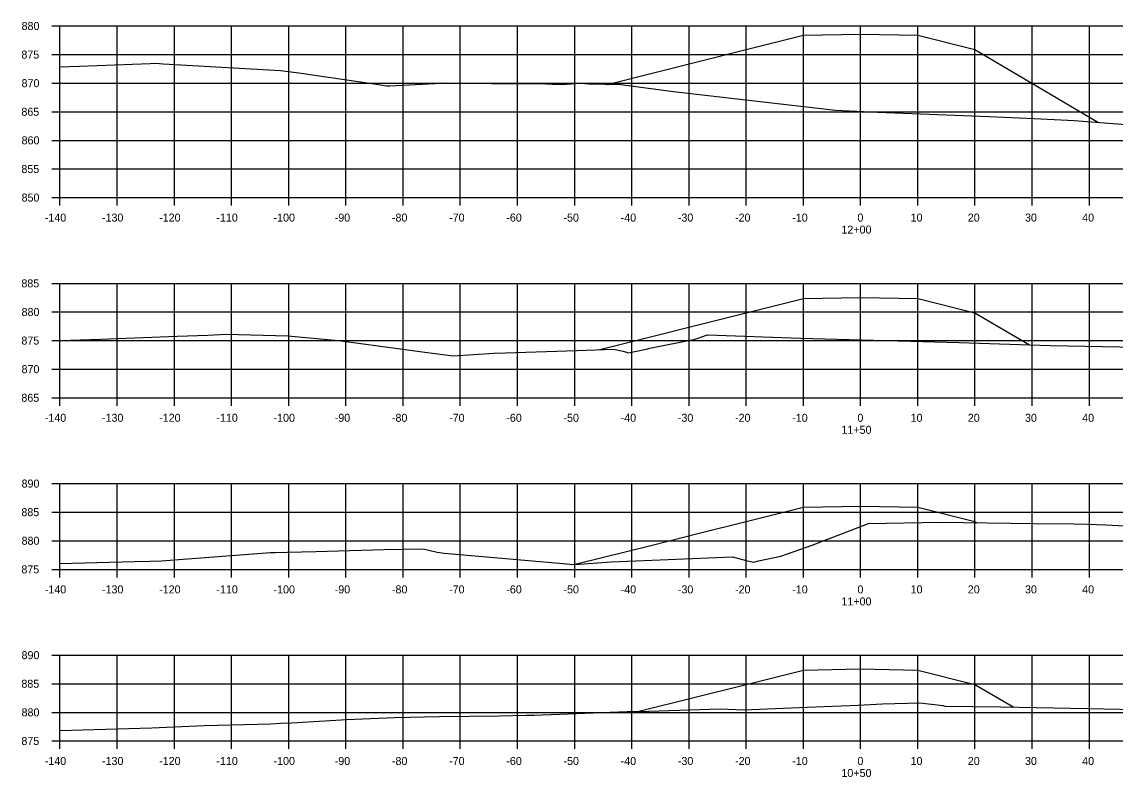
# Model space of a CAD drawing. Extents: x 1098669 to 1198896, y 698679 to 704410.
# Drawn here: x 1110634.5 to 1110825.7, y 701652.8 to 701784.8 of the extents above; entities that cross this region are included whole.
import ezdxf

# ---------------------------------------------------------------- set-up
doc = ezdxf.new("R2010")
doc.units = 0
for name, color, linetype in [('Proposed Surface', 7, 'Continuous'), ('R_Axis', 7, 'Continuous'), ('R_Axis Annot', 7, 'Continuous'), ('R_Fin Surface', 7, 'Continuous'), ('R_Grid', 7, 'Continuous')]:
    doc.layers.add(name, color=color, linetype=linetype)

msp = doc.modelspace()

# ---------------------------------------------------------------- linework, layer by layer
at = {"layer": 'Proposed Surface'}
for points in [[(1110641.16, 701777.01), (1110644.58, 701777.09), (1110656.9, 701777.56), (1110657.91, 701777.6), (1110659.22, 701777.52), (1110679.74, 701776.34), (1110682.93, 701775.94), (1110696.1, 701774), (1110697.88, 701773.74), (1110698.32, 701773.67), (1110698.85, 701773.69), (1110708.98, 701774.17), (1110716.6, 701774.06), (1110725.18, 701774.08), (1110727.28, 701773.95), (1110728.95, 701773.9), (1110731.29, 701774.08), (1110732.23, 701774.11), (1110733.55, 701774), (1110739.23, 701773.87), (1110748.41, 701772.69), (1110776.76, 701769.4), (1110784.13, 701769.05), (1110803.65, 701768.28), (1110811.52, 701767.97), (1110818.51, 701767.61), (1110851.8, 701765.03)], [(1110641.16, 701729.16), (1110648.32, 701729.35), (1110661.64, 701729.88), (1110666.99, 701730.08), (1110670.21, 701730.23), (1110681.02, 701729.94), (1110689.84, 701729.12), (1110690.3, 701729.08), (1110704.09, 701727.22), (1110709.94, 701726.49), (1110717.04, 701726.9), (1110719.06, 701727.01), (1110731.6, 701727.38), (1110737.93, 701727.61), (1110739.61, 701727.29), (1110740.56, 701726.98), (1110743.66, 701727.64), (1110744.3, 701727.81), (1110752.22, 701729.36), (1110754.4, 701730.11), (1110770.67, 701729.54), (1110798.38, 701728.78), (1110814.33, 701728.24), (1110832.59, 701727.9)], [(1110641.16, 701690.17), (1110654.19, 701690.48), (1110656.9, 701690.54), (1110658.9, 701690.6), (1110677.95, 701692.06), (1110678.78, 701692.1), (1110680.9, 701692.14), (1110685.87, 701692.23), (1110687.9, 701692.3), (1110697.84, 701692.62), (1110704.66, 701692.73), (1110707.09, 701692.12), (1110708.34, 701691.96), (1110729.12, 701690.14), (1110730.31, 701690.05), (1110731.16, 701689.99), (1110732, 701690.04), (1110737.55, 701690.43), (1110741.86, 701690.64), (1110747.52, 701690.87), (1110758.76, 701691.33), (1110761.17, 701690.68), (1110762.41, 701690.36), (1110763.31, 701690.61), (1110767.22, 701691.42), (1110772.71, 701693.36), (1110782.52, 701697.12), (1110795.05, 701697.39), (1110811.45, 701697.14), (1110818.44, 701697.08), (1110820.76, 701697.05), (1110824.05, 701696.94), (1110838.5, 701696.15)], [(1110641.16, 701660.94), (1110657.21, 701661.41), (1110666.36, 701661.86), (1110678, 701662.15), (1110679.72, 701662.25), (1110681.63, 701662.3), (1110691.34, 701662.88), (1110699.68, 701663.22), (1110707.55, 701663.38), (1110717.97, 701663.55), (1110722.68, 701663.63), (1110724.08, 701663.65), (1110740.32, 701664.3), (1110744.13, 701664.35), (1110756.61, 701664.73), (1110760.67, 701664.55), (1110771.81, 701665.05), (1110780.71, 701665.38), (1110785, 701665.62), (1110791.53, 701665.78), (1110795.05, 701665.38), (1110795.41, 701665.34), (1110795.55, 701665.32), (1110795.93, 701665.24), (1110805.6, 701665.08), (1110811.86, 701664.96), (1110820.88, 701664.81), (1110832.15, 701664.6)]]:
    msp.add_lwpolyline(points, dxfattribs=at)
at = {"layer": 'R_Axis'}
for p, q in [((1110639.76, 701784.13), (1110641.16, 701784.13)), ((1110641.16, 701754.13), (1110641.16, 701784.13)), ((1110639.76, 701779.13), (1110641.16, 701779.13)), ((1110639.76, 701774.13), (1110641.16, 701774.13)), ((1110639.76, 701769.13), (1110641.16, 701769.13)), ((1110639.76, 701764.13), (1110641.16, 701764.13)), ((1110639.76, 701759.13), (1110641.16, 701759.13)), ((1110639.76, 701754.13), (1110641.16, 701754.13)), ((1110641.16, 701754.13), (1110921.16, 701754.13)), ((1110641.16, 701752.73), (1110641.16, 701754.13)), ((1110651.16, 701752.73), (1110651.16, 701754.13)), ((1110661.16, 701752.73), (1110661.16, 701754.13)), ((1110671.16, 701752.73), (1110671.16, 701754.13)), ((1110681.16, 701752.73), (1110681.16, 701754.13)), ((1110691.16, 701752.73), (1110691.16, 701754.13)), ((1110701.16, 701752.73), (1110701.16, 701754.13)), ((1110711.16, 701752.73), (1110711.16, 701754.13)), ((1110721.16, 701752.73), (1110721.16, 701754.13)), ((1110731.16, 701752.73), (1110731.16, 701754.13)), ((1110741.16, 701752.73), (1110741.16, 701754.13)), ((1110751.16, 701752.73), (1110751.16, 701754.13)), ((1110761.16, 701752.73), (1110761.16, 701754.13)), ((1110771.16, 701752.73), (1110771.16, 701754.13)), ((1110781.16, 701752.73), (1110781.16, 701754.13)), ((1110791.16, 701752.73), (1110791.16, 701754.13)), ((1110801.16, 701752.73), (1110801.16, 701754.13)), ((1110811.16, 701752.73), (1110811.16, 701754.13)), ((1110821.16, 701752.73), (1110821.16, 701754.13)), ((1110639.76, 701739.13), (1110641.16, 701739.13)), ((1110641.16, 701719.13), (1110641.16, 701739.13)), ((1110639.76, 701734.13), (1110641.16, 701734.13)), ((1110639.76, 701729.13), (1110641.16, 701729.13)), ((1110639.76, 701724.13), (1110641.16, 701724.13)), ((1110639.76, 701719.13), (1110641.16, 701719.13)), ((1110641.16, 701719.13), (1110921.16, 701719.13)), ((1110641.16, 701717.73), (1110641.16, 701719.13)), ((1110651.16, 701717.73), (1110651.16, 701719.13)), ((1110661.16, 701717.73), (1110661.16, 701719.13)), ((1110671.16, 701717.73), (1110671.16, 701719.13)), ((1110681.16, 701717.73), (1110681.16, 701719.13)), ((1110691.16, 701717.73), (1110691.16, 701719.13)), ((1110701.16, 701717.73), (1110701.16, 701719.13)), ((1110711.16, 701717.73), (1110711.16, 701719.13)), ((1110721.16, 701717.73), (1110721.16, 701719.13)), ((1110731.16, 701717.73), (1110731.16, 701719.13)), ((1110741.16, 701717.73), (1110741.16, 701719.13)), ((1110751.16, 701717.73), (1110751.16, 701719.13)), ((1110761.16, 701717.73), (1110761.16, 701719.13)), ((1110771.16, 701717.73), (1110771.16, 701719.13)), ((1110781.16, 701717.73), (1110781.16, 701719.13)), ((1110791.16, 701717.73), (1110791.16, 701719.13)), ((1110801.16, 701717.73), (1110801.16, 701719.13)), ((1110811.16, 701717.73), (1110811.16, 701719.13)), ((1110821.16, 701717.73), (1110821.16, 701719.13)), ((1110639.76, 701704.13), (1110641.16, 701704.13)), ((1110641.16, 701689.13), (1110641.16, 701704.13)), ((1110639.76, 701699.13), (1110641.16, 701699.13)), ((1110639.76, 701694.13), (1110641.16, 701694.13)), ((1110639.76, 701689.13), (1110641.16, 701689.13)), ((1110641.16, 701689.13), (1110921.16, 701689.13)), ((1110641.16, 701687.73), (1110641.16, 701689.13)), ((1110651.16, 701687.73), (1110651.16, 701689.13)), ((1110661.16, 701687.73), (1110661.16, 701689.13)), ((1110671.16, 701687.73), (1110671.16, 701689.13)), ((1110681.16, 701687.73), (1110681.16, 701689.13)), ((1110691.16, 701687.73), (1110691.16, 701689.13)), ((1110701.16, 701687.73), (1110701.16, 701689.13)), ((1110711.16, 701687.73), (1110711.16, 701689.13)), ((1110721.16, 701687.73), (1110721.16, 701689.13)), ((1110731.16, 701687.73), (1110731.16, 701689.13)), ((1110741.16, 701687.73), (1110741.16, 701689.13)), ((1110751.16, 701687.73), (1110751.16, 701689.13)), ((1110761.16, 701687.73), (1110761.16, 701689.13)), ((1110771.16, 701687.73), (1110771.16, 701689.13)), ((1110781.16, 701687.73), (1110781.16, 701689.13)), ((1110791.16, 701687.73), (1110791.16, 701689.13)), ((1110801.16, 701687.73), (1110801.16, 701689.13)), ((1110811.16, 701687.73), (1110811.16, 701689.13)), ((1110821.16, 701687.73), (1110821.16, 701689.13)), ((1110639.76, 701674.13), (1110641.16, 701674.13)), ((1110641.16, 701659.13), (1110641.16, 701674.13)), ((1110639.76, 701669.13), (1110641.16, 701669.13)), ((1110639.76, 701664.13), (1110641.16, 701664.13)), ((1110639.76, 701659.13), (1110641.16, 701659.13)), ((1110641.16, 701659.13), (1110921.16, 701659.13)), ((1110641.16, 701657.73), (1110641.16, 701659.13)), ((1110651.16, 701657.73), (1110651.16, 701659.13)), ((1110661.16, 701657.73), (1110661.16, 701659.13)), ((1110671.16, 701657.73), (1110671.16, 701659.13)), ((1110681.16, 701657.73), (1110681.16, 701659.13)), ((1110691.16, 701657.73), (1110691.16, 701659.13)), ((1110701.16, 701657.73), (1110701.16, 701659.13)), ((1110711.16, 701657.73), (1110711.16, 701659.13)), ((1110721.16, 701657.73), (1110721.16, 701659.13)), ((1110731.16, 701657.73), (1110731.16, 701659.13)), ((1110741.16, 701657.73), (1110741.16, 701659.13)), ((1110751.16, 701657.73), (1110751.16, 701659.13)), ((1110761.16, 701657.73), (1110761.16, 701659.13)), ((1110771.16, 701657.73), (1110771.16, 701659.13)), ((1110781.16, 701657.73), (1110781.16, 701659.13)), ((1110791.16, 701657.73), (1110791.16, 701659.13)), ((1110801.16, 701657.73), (1110801.16, 701659.13)), ((1110811.16, 701657.73), (1110811.16, 701659.13)), ((1110821.16, 701657.73), (1110821.16, 701659.13))]:
    msp.add_line(p, q, dxfattribs=at)
at = {"layer": 'R_Fin Surface'}
for points in [[(1110736.84, 701773.92), (1110761.16, 701780), (1110771.16, 701782.5), (1110781.16, 701782.7), (1110791.16, 701782.5), (1110801.16, 701780), (1110808.55, 701775.64), (1110822.74, 701767.28)], [(1110735.31, 701727.51), (1110761.16, 701733.98), (1110771.16, 701736.48), (1110781.16, 701736.68), (1110791.16, 701736.48), (1110801.16, 701733.98), (1110810.68, 701728.36)], [(1110731.16, 701689.99), (1110731.38, 701690.05), (1110731.5, 701690.08), (1110744.68, 701693.38), (1110752.9, 701695.43), (1110761.16, 701697.49), (1110771.16, 701699.99), (1110781.16, 701700.19), (1110791.16, 701699.99), (1110801.16, 701697.49), (1110801.5, 701697.29)], [(1110742.35, 701664.33), (1110761.16, 701669.03), (1110771.16, 701671.53), (1110781.16, 701671.73), (1110791.16, 701671.53), (1110801.16, 701669.03), (1110807.93, 701665.04)]]:
    msp.add_lwpolyline(points, dxfattribs=at)
at = {"layer": 'R_Grid'}
for p, q in [((1110641.16, 701784.13), (1110921.16, 701784.13)), ((1110641.16, 701754.13), (1110641.16, 701784.13)), ((1110651.16, 701754.13), (1110651.16, 701784.13)), ((1110661.16, 701754.13), (1110661.16, 701784.13)), ((1110671.16, 701754.13), (1110671.16, 701784.13)), ((1110681.16, 701754.13), (1110681.16, 701784.13)), ((1110691.16, 701754.13), (1110691.16, 701784.13)), ((1110701.16, 701754.13), (1110701.16, 701784.13)), ((1110711.16, 701754.13), (1110711.16, 701784.13)), ((1110721.16, 701754.13), (1110721.16, 701784.13)), ((1110731.16, 701754.13), (1110731.16, 701784.13)), ((1110741.16, 701754.13), (1110741.16, 701784.13)), ((1110751.16, 701754.13), (1110751.16, 701784.13)), ((1110761.16, 701754.13), (1110761.16, 701784.13)), ((1110771.16, 701754.13), (1110771.16, 701784.13)), ((1110781.16, 701754.13), (1110781.16, 701784.13)), ((1110791.16, 701754.13), (1110791.16, 701784.13)), ((1110801.16, 701754.13), (1110801.16, 701784.13)), ((1110811.16, 701754.13), (1110811.16, 701784.13)), ((1110821.16, 701754.13), (1110821.16, 701784.13)), ((1110641.16, 701779.13), (1110921.16, 701779.13)), ((1110641.16, 701774.13), (1110921.16, 701774.13)), ((1110641.16, 701769.13), (1110921.16, 701769.13)), ((1110641.16, 701764.13), (1110921.16, 701764.13)), ((1110641.16, 701759.13), (1110921.16, 701759.13)), ((1110641.16, 701754.13), (1110921.16, 701754.13)), ((1110641.16, 701739.13), (1110921.16, 701739.13)), ((1110641.16, 701719.13), (1110641.16, 701739.13)), ((1110651.16, 701719.13), (1110651.16, 701739.13)), ((1110661.16, 701719.13), (1110661.16, 701739.13)), ((1110671.16, 701719.13), (1110671.16, 701739.13)), ((1110681.16, 701719.13), (1110681.16, 701739.13)), ((1110691.16, 701719.13), (1110691.16, 701739.13)), ((1110701.16, 701719.13), (1110701.16, 701739.13)), ((1110711.16, 701719.13), (1110711.16, 701739.13)), ((1110721.16, 701719.13), (1110721.16, 701739.13)), ((1110731.16, 701719.13), (1110731.16, 701739.13)), ((1110741.16, 701719.13), (1110741.16, 701739.13)), ((1110751.16, 701719.13), (1110751.16, 701739.13)), ((1110761.16, 701719.13), (1110761.16, 701739.13)), ((1110771.16, 701719.13), (1110771.16, 701739.13)), ((1110781.16, 701719.13), (1110781.16, 701739.13)), ((1110791.16, 701719.13), (1110791.16, 701739.13)), ((1110801.16, 701719.13), (1110801.16, 701739.13)), ((1110811.16, 701719.13), (1110811.16, 701739.13)), ((1110821.16, 701719.13), (1110821.16, 701739.13)), ((1110641.16, 701734.13), (1110921.16, 701734.13)), ((1110641.16, 701729.13), (1110921.16, 701729.13)), ((1110641.16, 701724.13), (1110921.16, 701724.13)), ((1110641.16, 701719.13), (1110921.16, 701719.13)), ((1110641.16, 701704.13), (1110921.16, 701704.13)), ((1110641.16, 701689.13), (1110641.16, 701704.13)), ((1110651.16, 701689.13), (1110651.16, 701704.13)), ((1110661.16, 701689.13), (1110661.16, 701704.13)), ((1110671.16, 701689.13), (1110671.16, 701704.13)), ((1110681.16, 701689.13), (1110681.16, 701704.13)), ((1110691.16, 701689.13), (1110691.16, 701704.13)), ((1110701.16, 701689.13), (1110701.16, 701704.13)), ((1110711.16, 701689.13), (1110711.16, 701704.13)), ((1110721.16, 701689.13), (1110721.16, 701704.13)), ((1110731.16, 701689.13), (1110731.16, 701704.13)), ((1110741.16, 701689.13), (1110741.16, 701704.13)), ((1110751.16, 701689.13), (1110751.16, 701704.13)), ((1110761.16, 701689.13), (1110761.16, 701704.13)), ((1110771.16, 701689.13), (1110771.16, 701704.13)), ((1110781.16, 701689.13), (1110781.16, 701704.13)), ((1110791.16, 701689.13), (1110791.16, 701704.13)), ((1110801.16, 701689.13), (1110801.16, 701704.13)), ((1110811.16, 701689.13), (1110811.16, 701704.13)), ((1110821.16, 701689.13), (1110821.16, 701704.13)), ((1110641.16, 701699.13), (1110921.16, 701699.13)), ((1110641.16, 701694.13), (1110921.16, 701694.13)), ((1110641.16, 701689.13), (1110921.16, 701689.13)), ((1110641.16, 701674.13), (1110921.16, 701674.13)), ((1110641.16, 701659.13), (1110641.16, 701674.13)), ((1110651.16, 701659.13), (1110651.16, 701674.13)), ((1110661.16, 701659.13), (1110661.16, 701674.13)), ((1110671.16, 701659.13), (1110671.16, 701674.13)), ((1110681.16, 701659.13), (1110681.16, 701674.13)), ((1110691.16, 701659.13), (1110691.16, 701674.13)), ((1110701.16, 701659.13), (1110701.16, 701674.13)), ((1110711.16, 701659.13), (1110711.16, 701674.13)), ((1110721.16, 701659.13), (1110721.16, 701674.13)), ((1110731.16, 701659.13), (1110731.16, 701674.13)), ((1110741.16, 701659.13), (1110741.16, 701674.13)), ((1110751.16, 701659.13), (1110751.16, 701674.13)), ((1110761.16, 701659.13), (1110761.16, 701674.13)), ((1110771.16, 701659.13), (1110771.16, 701674.13)), ((1110781.16, 701659.13), (1110781.16, 701674.13)), ((1110791.16, 701659.13), (1110791.16, 701674.13)), ((1110801.16, 701659.13), (1110801.16, 701674.13)), ((1110811.16, 701659.13), (1110811.16, 701674.13)), ((1110821.16, 701659.13), (1110821.16, 701674.13)), ((1110641.16, 701669.13), (1110921.16, 701669.13)), ((1110641.16, 701664.13), (1110921.16, 701664.13)), ((1110641.16, 701659.13), (1110921.16, 701659.13))]:
    msp.add_line(p, q, dxfattribs=at)

# ---------------------------------------------------------------- texts
at = {"layer": 'R_Axis Annot'}
for s, p in [('880', (1110634.44, 701783.43)), ('875', (1110634.41, 701778.43)), ('870', (1110634.44, 701773.43)), ('865', (1110634.41, 701768.43)), ('860', (1110634.44, 701763.43)), ('855', (1110634.41, 701758.43)), ('850', (1110634.44, 701753.43)), ('-140', (1110638.5, 701749.93)), ('-130', (1110648.5, 701749.93)), ('-120', (1110658.5, 701749.93)), ('-110', (1110668.5, 701749.93)), ('-100', (1110678.5, 701749.93)), ('-90', (1110689.2, 701749.93)), ('-80', (1110699.2, 701749.93)), ('-70', (1110709.2, 701749.93)), ('-60', (1110719.2, 701749.93)), ('-50', (1110729.2, 701749.93)), ('-40', (1110739.2, 701749.93)), ('-30', (1110749.2, 701749.93)), ('-20', (1110759.2, 701749.93)), ('-10', (1110769.2, 701749.93)), ('0', (1110780.6, 701749.93)), ('10', (1110789.9, 701749.93)), ('20', (1110799.9, 701749.93)), ('30', (1110809.9, 701749.93)), ('40', (1110819.9, 701749.93)), ('12+00', (1110777.8, 701747.83)), ('885', (1110634.41, 701738.43)), ('880', (1110634.44, 701733.43)), ('875', (1110634.41, 701728.43)), ('870', (1110634.44, 701723.43)), ('865', (1110634.41, 701718.43)), ('-140', (1110638.5, 701714.93)), ('-130', (1110648.5, 701714.93)), ('-120', (1110658.5, 701714.93)), ('-110', (1110668.5, 701714.93)), ('-100', (1110678.5, 701714.93)), ('-90', (1110689.2, 701714.93)), ('-80', (1110699.2, 701714.93)), ('-70', (1110709.2, 701714.93)), ('-60', (1110719.2, 701714.93)), ('-50', (1110729.2, 701714.93)), ('-40', (1110739.2, 701714.93)), ('-30', (1110749.2, 701714.93)), ('-20', (1110759.2, 701714.93)), ('-10', (1110769.2, 701714.93)), ('0', (1110780.6, 701714.93)), ('10', (1110789.9, 701714.93)), ('20', (1110799.9, 701714.93)), ('30', (1110809.9, 701714.93)), ('40', (1110819.9, 701714.93)), ('11+50', (1110777.8, 701712.83)), ('890', (1110634.44, 701703.43)), ('885', (1110634.41, 701698.43)), ('880', (1110634.44, 701693.43)), ('875', (1110634.41, 701688.43)), ('-140', (1110638.5, 701684.93)), ('-130', (1110648.5, 701684.93)), ('-120', (1110658.5, 701684.93)), ('-110', (1110668.5, 701684.93)), ('-100', (1110678.5, 701684.93)), ('-90', (1110689.2, 701684.93)), ('-80', (1110699.2, 701684.93)), ('-70', (1110709.2, 701684.93)), ('-60', (1110719.2, 701684.93)), ('-50', (1110729.2, 701684.93)), ('-40', (1110739.2, 701684.93)), ('-30', (1110749.2, 701684.93)), ('-20', (1110759.2, 701684.93)), ('-10', (1110769.2, 701684.93)), ('0', (1110780.6, 701684.93)), ('10', (1110789.9, 701684.93)), ('20', (1110799.9, 701684.93)), ('30', (1110809.9, 701684.93)), ('40', (1110819.9, 701684.93)), ('11+00', (1110777.8, 701682.83)), ('890', (1110634.44, 701673.43)), ('885', (1110634.41, 701668.43)), ('880', (1110634.44, 701663.43)), ('875', (1110634.41, 701658.43)), ('-140', (1110638.5, 701654.93)), ('-130', (1110648.5, 701654.93)), ('-120', (1110658.5, 701654.93)), ('-110', (1110668.5, 701654.93)), ('-100', (1110678.5, 701654.93)), ('-90', (1110689.2, 701654.93)), ('-80', (1110699.2, 701654.93)), ('-70', (1110709.2, 701654.93)), ('-60', (1110719.2, 701654.93)), ('-50', (1110729.2, 701654.93)), ('-40', (1110739.2, 701654.93)), ('-30', (1110749.2, 701654.93)), ('-20', (1110759.2, 701654.93)), ('-10', (1110769.2, 701654.93)), ('0', (1110780.6, 701654.93)), ('10', (1110789.9, 701654.93)), ('20', (1110799.9, 701654.93)), ('30', (1110809.9, 701654.93)), ('40', (1110819.9, 701654.93)), ('10+50', (1110777.8, 701652.83))]:
    msp.add_text(s, height=1.4, dxfattribs=at).set_placement(p)

doc.saveas('drawing.dxf')
